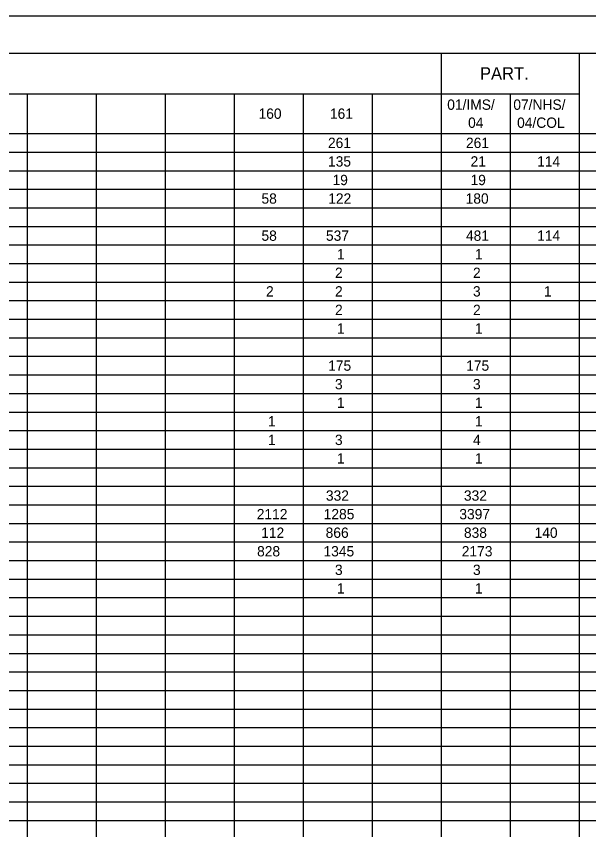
# Model space of a CAD drawing. Extents: x 1826847 to 2221677, y 500657 to 714743.
# Drawn here: x 1827314 to 1827702, y 714191 to 714743 of the extents above; entities that cross this region are included whole.
import ezdxf

# ---------------------------------------------------------------- set-up
doc = ezdxf.new("R2010")
doc.units = 0
for name, color, linetype in [('SH_Border', 7, 'Continuous'), ('SH_Cut_Line', 7, 'Continuous'), ('SH_Data', 7, 'Continuous'), ('SH_Text', 7, 'Continuous')]:
    doc.layers.add(name, color=color, linetype=linetype)

msp = doc.modelspace()

# ---------------------------------------------------------------- linework, layer by layer
at = {"layer": 'SH_Border'}
msp.add_lwpolyline([(1826946.62, 714718.08), (1828521.62, 714718.08), (1828521.62, 713668.08), (1826946.62, 713668.08)], close=True, dxfattribs=at)
at = {"layer": 'SH_Cut_Line'}
msp.add_lwpolyline([(1826846.62, 713643.08), (1828546.62, 713643.08), (1828546.62, 714743.08), (1826846.62, 714743.08)], close=True, dxfattribs=at)
at = {"layer": 'SH_Data'}
for p, q in [((1827274.22, 714718.08), (1827321.02, 714718.08)), ((1827321.02, 714718.08), (1827367.82, 714718.08)), ((1827367.82, 714718.08), (1827414.62, 714718.08)), ((1827414.62, 714718.08), (1827461.42, 714718.08)), ((1827461.42, 714718.08), (1827648.62, 714718.08)), ((1827601.82, 714718.08), (1827601.82, 714663.48)), ((1827648.62, 714718.08), (1827808.82, 714718.08)), ((1827695.42, 714718.08), (1827695.42, 714663.48)), ((1827274.22, 714690.48), (1827321.02, 714690.48)), ((1827321.02, 714690.48), (1827367.82, 714690.48)), ((1827321.02, 714690.48), (1827321.02, 714663.48)), ((1827367.82, 714690.48), (1827414.62, 714690.48)), ((1827367.82, 714690.48), (1827367.82, 714663.48)), ((1827414.62, 714690.48), (1827461.42, 714690.48)), ((1827414.62, 714690.48), (1827414.62, 714663.48)), ((1827461.42, 714690.48), (1827648.62, 714690.48)), ((1827461.42, 714690.48), (1827461.42, 714663.48)), ((1827508.22, 714690.48), (1827508.22, 714663.48)), ((1827555.02, 714690.48), (1827555.02, 714663.48)), ((1827648.62, 714690.48), (1827695.42, 714690.48)), ((1827648.62, 714690.48), (1827648.62, 714663.48)), ((1827274.22, 714663.48), (1827321.02, 714663.48)), ((1827321.02, 714663.48), (1827367.82, 714663.48)), ((1827321.02, 714663.48), (1827321.02, 714600.48)), ((1827367.82, 714663.48), (1827414.62, 714663.48)), ((1827367.82, 714663.48), (1827367.82, 714600.48)), ((1827414.62, 714663.48), (1827461.42, 714663.48)), ((1827414.62, 714663.48), (1827414.62, 714600.48)), ((1827461.42, 714663.48), (1827648.62, 714663.48)), ((1827461.42, 714663.48), (1827461.42, 714600.48)), ((1827508.22, 714663.48), (1827508.22, 714600.48)), ((1827555.02, 714663.48), (1827555.02, 714600.48)), ((1827601.82, 714663.48), (1827601.82, 714600.48)), ((1827648.62, 714663.48), (1827808.82, 714663.48)), ((1827648.62, 714663.48), (1827648.62, 714600.48)), ((1827695.42, 714663.48), (1827695.42, 714600.48)), ((1827274.22, 714650.88), (1827321.02, 714650.88)), ((1827321.02, 714650.88), (1827367.82, 714650.88)), ((1827367.82, 714650.88), (1827414.62, 714650.88)), ((1827414.62, 714650.88), (1827461.42, 714650.88)), ((1827461.42, 714650.88), (1827648.62, 714650.88)), ((1827648.62, 714650.88), (1827808.82, 714650.88)), ((1827274.22, 714638.28), (1827321.02, 714638.28)), ((1827321.02, 714638.28), (1827367.82, 714638.28)), ((1827367.82, 714638.28), (1827414.62, 714638.28)), ((1827414.62, 714638.28), (1827461.42, 714638.28)), ((1827461.42, 714638.28), (1827648.62, 714638.28)), ((1827648.62, 714638.28), (1827808.82, 714638.28)), ((1827274.22, 714625.68), (1827321.02, 714625.68)), ((1827321.02, 714625.68), (1827367.82, 714625.68)), ((1827367.82, 714625.68), (1827414.62, 714625.68)), ((1827414.62, 714625.68), (1827461.42, 714625.68)), ((1827461.42, 714625.68), (1827648.62, 714625.68)), ((1827648.62, 714625.68), (1827808.82, 714625.68)), ((1827274.22, 714613.08), (1827321.02, 714613.08)), ((1827321.02, 714613.08), (1827367.82, 714613.08)), ((1827367.82, 714613.08), (1827414.62, 714613.08)), ((1827414.62, 714613.08), (1827461.42, 714613.08)), ((1827461.42, 714613.08), (1827648.62, 714613.08)), ((1827648.62, 714613.08), (1827808.82, 714613.08)), ((1827274.22, 714600.48), (1827321.02, 714600.48)), ((1827321.02, 714600.48), (1827367.82, 714600.48)), ((1827321.02, 714600.48), (1827321.02, 714587.88)), ((1827367.82, 714600.48), (1827414.62, 714600.48)), ((1827367.82, 714600.48), (1827367.82, 714587.88)), ((1827414.62, 714600.48), (1827461.42, 714600.48)), ((1827414.62, 714600.48), (1827414.62, 714587.88)), ((1827461.42, 714600.48), (1827648.62, 714600.48)), ((1827461.42, 714600.48), (1827461.42, 714587.88)), ((1827508.22, 714600.48), (1827508.22, 714587.88)), ((1827555.02, 714600.48), (1827555.02, 714587.88)), ((1827601.82, 714600.48), (1827601.82, 714587.88)), ((1827648.62, 714600.48), (1827808.82, 714600.48)), ((1827648.62, 714600.48), (1827648.62, 714587.88)), ((1827695.42, 714600.48), (1827695.42, 714587.88)), ((1827274.22, 714587.88), (1827321.02, 714587.88)), ((1827321.02, 714587.88), (1827367.82, 714587.88)), ((1827321.02, 714587.88), (1827321.02, 714575.28)), ((1827367.82, 714587.88), (1827414.62, 714587.88)), ((1827367.82, 714587.88), (1827367.82, 714575.28)), ((1827414.62, 714587.88), (1827461.42, 714587.88)), ((1827414.62, 714587.88), (1827414.62, 714575.28)), ((1827461.42, 714587.88), (1827648.62, 714587.88)), ((1827461.42, 714587.88), (1827461.42, 714575.28)), ((1827508.22, 714587.88), (1827508.22, 714575.28)), ((1827555.02, 714587.88), (1827555.02, 714575.28)), ((1827601.82, 714587.88), (1827601.82, 714575.28)), ((1827648.62, 714587.88), (1827808.82, 714587.88)), ((1827648.62, 714587.88), (1827648.62, 714575.28)), ((1827695.42, 714587.88), (1827695.42, 714575.28)), ((1827274.22, 714575.28), (1827321.02, 714575.28)), ((1827321.02, 714575.28), (1827367.82, 714575.28)), ((1827321.02, 714575.28), (1827321.02, 714562.68)), ((1827367.82, 714575.28), (1827414.62, 714575.28)), ((1827367.82, 714575.28), (1827367.82, 714562.68)), ((1827414.62, 714575.28), (1827461.42, 714575.28)), ((1827414.62, 714575.28), (1827414.62, 714562.68)), ((1827461.42, 714575.28), (1827648.62, 714575.28)), ((1827461.42, 714575.28), (1827461.42, 714562.68)), ((1827508.22, 714575.28), (1827508.22, 714562.68)), ((1827555.02, 714575.28), (1827555.02, 714562.68)), ((1827601.82, 714575.28), (1827601.82, 714562.68)), ((1827648.62, 714575.28), (1827808.82, 714575.28)), ((1827648.62, 714575.28), (1827648.62, 714562.68)), ((1827695.42, 714575.28), (1827695.42, 714562.68)), ((1827274.22, 714562.68), (1827321.02, 714562.68)), ((1827321.02, 714562.68), (1827367.82, 714562.68)), ((1827321.02, 714562.68), (1827321.02, 714550.08)), ((1827367.82, 714562.68), (1827414.62, 714562.68)), ((1827367.82, 714562.68), (1827367.82, 714550.08)), ((1827414.62, 714562.68), (1827461.42, 714562.68)), ((1827414.62, 714562.68), (1827414.62, 714550.08)), ((1827461.42, 714562.68), (1827648.62, 714562.68)), ((1827461.42, 714562.68), (1827461.42, 714550.08)), ((1827508.22, 714562.68), (1827508.22, 714550.08)), ((1827555.02, 714562.68), (1827555.02, 714550.08)), ((1827601.82, 714562.68), (1827601.82, 714550.08)), ((1827648.62, 714562.68), (1827808.82, 714562.68)), ((1827648.62, 714562.68), (1827648.62, 714550.08)), ((1827695.42, 714562.68), (1827695.42, 714550.08)), ((1827274.22, 714550.08), (1827321.02, 714550.08)), ((1827321.02, 714550.08), (1827367.82, 714550.08)), ((1827321.02, 714550.08), (1827321.02, 714537.48)), ((1827367.82, 714550.08), (1827414.62, 714550.08)), ((1827367.82, 714550.08), (1827367.82, 714537.48)), ((1827414.62, 714550.08), (1827461.42, 714550.08)), ((1827414.62, 714550.08), (1827414.62, 714537.48)), ((1827461.42, 714550.08), (1827648.62, 714550.08)), ((1827461.42, 714550.08), (1827461.42, 714537.48)), ((1827508.22, 714550.08), (1827508.22, 714537.48)), ((1827555.02, 714550.08), (1827555.02, 714537.48)), ((1827601.82, 714550.08), (1827601.82, 714537.48)), ((1827648.62, 714550.08), (1827808.82, 714550.08)), ((1827648.62, 714550.08), (1827648.62, 714537.48)), ((1827695.42, 714550.08), (1827695.42, 714537.48)), ((1827274.22, 714537.48), (1827321.02, 714537.48)), ((1827321.02, 714537.48), (1827367.82, 714537.48)), ((1827321.02, 714537.48), (1827321.02, 714524.88)), ((1827367.82, 714537.48), (1827414.62, 714537.48)), ((1827367.82, 714537.48), (1827367.82, 714524.88)), ((1827414.62, 714537.48), (1827461.42, 714537.48)), ((1827414.62, 714537.48), (1827414.62, 714524.88)), ((1827461.42, 714537.48), (1827648.62, 714537.48)), ((1827461.42, 714537.48), (1827461.42, 714524.88)), ((1827508.22, 714537.48), (1827508.22, 714524.88)), ((1827555.02, 714537.48), (1827555.02, 714524.88)), ((1827601.82, 714537.48), (1827601.82, 714524.88)), ((1827648.62, 714537.48), (1827808.82, 714537.48)), ((1827648.62, 714537.48), (1827648.62, 714524.88)), ((1827695.42, 714537.48), (1827695.42, 714524.88)), ((1827274.22, 714524.88), (1827321.02, 714524.88)), ((1827321.02, 714524.88), (1827367.82, 714524.88)), ((1827321.02, 714524.88), (1827321.02, 714512.28)), ((1827367.82, 714524.88), (1827414.62, 714524.88)), ((1827367.82, 714524.88), (1827367.82, 714512.28)), ((1827414.62, 714524.88), (1827461.42, 714524.88)), ((1827414.62, 714524.88), (1827414.62, 714512.28)), ((1827461.42, 714524.88), (1827648.62, 714524.88)), ((1827461.42, 714524.88), (1827461.42, 714512.28)), ((1827508.22, 714524.88), (1827508.22, 714512.28)), ((1827555.02, 714524.88), (1827555.02, 714512.28)), ((1827601.82, 714524.88), (1827601.82, 714512.28)), ((1827648.62, 714524.88), (1827808.82, 714524.88)), ((1827648.62, 714524.88), (1827648.62, 714512.28)), ((1827695.42, 714524.88), (1827695.42, 714512.28)), ((1827274.22, 714512.28), (1827321.02, 714512.28)), ((1827321.02, 714512.28), (1827367.82, 714512.28)), ((1827321.02, 714512.28), (1827321.02, 714499.68)), ((1827367.82, 714512.28), (1827414.62, 714512.28)), ((1827367.82, 714512.28), (1827367.82, 714499.68)), ((1827414.62, 714512.28), (1827461.42, 714512.28)), ((1827414.62, 714512.28), (1827414.62, 714499.68)), ((1827461.42, 714512.28), (1827648.62, 714512.28)), ((1827461.42, 714512.28), (1827461.42, 714499.68)), ((1827508.22, 714512.28), (1827508.22, 714499.68)), ((1827555.02, 714512.28), (1827555.02, 714499.68)), ((1827601.82, 714512.28), (1827601.82, 714499.68)), ((1827648.62, 714512.28), (1827808.82, 714512.28)), ((1827648.62, 714512.28), (1827648.62, 714499.68)), ((1827695.42, 714512.28), (1827695.42, 714499.68)), ((1827274.22, 714499.68), (1827321.02, 714499.68)), ((1827321.02, 714499.68), (1827367.82, 714499.68)), ((1827321.02, 714499.68), (1827321.02, 714487.08)), ((1827367.82, 714499.68), (1827414.62, 714499.68)), ((1827367.82, 714499.68), (1827367.82, 714487.08)), ((1827414.62, 714499.68), (1827461.42, 714499.68)), ((1827414.62, 714499.68), (1827414.62, 714487.08)), ((1827461.42, 714499.68), (1827648.62, 714499.68)), ((1827461.42, 714499.68), (1827461.42, 714487.08)), ((1827508.22, 714499.68), (1827508.22, 714487.08)), ((1827555.02, 714499.68), (1827555.02, 714487.08)), ((1827601.82, 714499.68), (1827601.82, 714487.08)), ((1827648.62, 714499.68), (1827808.82, 714499.68)), ((1827648.62, 714499.68), (1827648.62, 714487.08)), ((1827695.42, 714499.68), (1827695.42, 714487.08)), ((1827274.22, 714487.08), (1827321.02, 714487.08)), ((1827321.02, 714487.08), (1827367.82, 714487.08)), ((1827321.02, 714487.08), (1827321.02, 714474.48)), ((1827367.82, 714487.08), (1827414.62, 714487.08)), ((1827367.82, 714487.08), (1827367.82, 714474.48)), ((1827414.62, 714487.08), (1827461.42, 714487.08)), ((1827414.62, 714487.08), (1827414.62, 714474.48)), ((1827461.42, 714487.08), (1827648.62, 714487.08)), ((1827461.42, 714487.08), (1827461.42, 714474.48)), ((1827508.22, 714487.08), (1827508.22, 714474.48)), ((1827555.02, 714487.08), (1827555.02, 714474.48)), ((1827601.82, 714487.08), (1827601.82, 714474.48)), ((1827648.62, 714487.08), (1827808.82, 714487.08)), ((1827648.62, 714487.08), (1827648.62, 714474.48)), ((1827695.42, 714487.08), (1827695.42, 714474.48)), ((1827274.22, 714474.48), (1827321.02, 714474.48)), ((1827321.02, 714474.48), (1827367.82, 714474.48)), ((1827321.02, 714474.48), (1827321.02, 714461.88)), ((1827367.82, 714474.48), (1827414.62, 714474.48)), ((1827367.82, 714474.48), (1827367.82, 714461.88)), ((1827414.62, 714474.48), (1827461.42, 714474.48)), ((1827414.62, 714474.48), (1827414.62, 714461.88)), ((1827461.42, 714474.48), (1827648.62, 714474.48)), ((1827461.42, 714474.48), (1827461.42, 714461.88)), ((1827508.22, 714474.48), (1827508.22, 714461.88)), ((1827555.02, 714474.48), (1827555.02, 714461.88)), ((1827601.82, 714474.48), (1827601.82, 714461.88)), ((1827648.62, 714474.48), (1827808.82, 714474.48)), ((1827648.62, 714474.48), (1827648.62, 714461.88)), ((1827695.42, 714474.48), (1827695.42, 714461.88)), ((1827274.22, 714461.88), (1827321.02, 714461.88)), ((1827321.02, 714461.88), (1827367.82, 714461.88)), ((1827321.02, 714461.88), (1827321.02, 714424.08)), ((1827367.82, 714461.88), (1827414.62, 714461.88)), ((1827367.82, 714461.88), (1827367.82, 714424.08)), ((1827414.62, 714461.88), (1827461.42, 714461.88)), ((1827414.62, 714461.88), (1827414.62, 714424.08)), ((1827461.42, 714461.88), (1827648.62, 714461.88)), ((1827461.42, 714461.88), (1827461.42, 714424.08)), ((1827508.22, 714461.88), (1827508.22, 714424.08)), ((1827555.02, 714461.88), (1827555.02, 714424.08)), ((1827601.82, 714461.88), (1827601.82, 714424.08)), ((1827648.62, 714461.88), (1827808.82, 714461.88)), ((1827648.62, 714461.88), (1827648.62, 714424.08)), ((1827695.42, 714461.88), (1827695.42, 714424.08)), ((1827274.22, 714449.28), (1827321.02, 714449.28)), ((1827321.02, 714449.28), (1827367.82, 714449.28)), ((1827367.82, 714449.28), (1827414.62, 714449.28)), ((1827414.62, 714449.28), (1827461.42, 714449.28)), ((1827461.42, 714449.28), (1827648.62, 714449.28)), ((1827648.62, 714449.28), (1827808.82, 714449.28)), ((1827274.22, 714436.68), (1827321.02, 714436.68)), ((1827321.02, 714436.68), (1827367.82, 714436.68)), ((1827367.82, 714436.68), (1827414.62, 714436.68)), ((1827414.62, 714436.68), (1827461.42, 714436.68)), ((1827461.42, 714436.68), (1827648.62, 714436.68)), ((1827648.62, 714436.68), (1827808.82, 714436.68)), ((1827274.22, 714424.08), (1827321.02, 714424.08)), ((1827321.02, 714424.08), (1827367.82, 714424.08)), ((1827321.02, 714424.08), (1827321.02, 714398.88)), ((1827367.82, 714424.08), (1827414.62, 714424.08)), ((1827367.82, 714424.08), (1827367.82, 714398.88)), ((1827414.62, 714424.08), (1827461.42, 714424.08)), ((1827414.62, 714424.08), (1827414.62, 714398.88)), ((1827461.42, 714424.08), (1827648.62, 714424.08)), ((1827461.42, 714424.08), (1827461.42, 714398.88)), ((1827508.22, 714424.08), (1827508.22, 714398.88)), ((1827555.02, 714424.08), (1827555.02, 714398.88)), ((1827601.82, 714424.08), (1827601.82, 714398.88)), ((1827648.62, 714424.08), (1827808.82, 714424.08)), ((1827648.62, 714424.08), (1827648.62, 714398.88)), ((1827695.42, 714424.08), (1827695.42, 714398.88)), ((1827274.22, 714411.48), (1827321.02, 714411.48)), ((1827321.02, 714411.48), (1827367.82, 714411.48)), ((1827367.82, 714411.48), (1827414.62, 714411.48)), ((1827414.62, 714411.48), (1827461.42, 714411.48)), ((1827461.42, 714411.48), (1827648.62, 714411.48)), ((1827648.62, 714411.48), (1827808.82, 714411.48)), ((1827274.22, 714398.88), (1827321.02, 714398.88)), ((1827321.02, 714398.88), (1827367.82, 714398.88)), ((1827321.02, 714398.88), (1827321.02, 714361.08)), ((1827367.82, 714398.88), (1827414.62, 714398.88)), ((1827367.82, 714398.88), (1827367.82, 714361.08)), ((1827414.62, 714398.88), (1827461.42, 714398.88)), ((1827414.62, 714398.88), (1827414.62, 714361.08)), ((1827461.42, 714398.88), (1827648.62, 714398.88)), ((1827461.42, 714398.88), (1827461.42, 714361.08)), ((1827508.22, 714398.88), (1827508.22, 714361.08)), ((1827555.02, 714398.88), (1827555.02, 714361.08)), ((1827601.82, 714398.88), (1827601.82, 714361.08)), ((1827648.62, 714398.88), (1827808.82, 714398.88)), ((1827648.62, 714398.88), (1827648.62, 714361.08)), ((1827695.42, 714398.88), (1827695.42, 714361.08)), ((1827274.22, 714386.28), (1827321.02, 714386.28)), ((1827321.02, 714386.28), (1827367.82, 714386.28)), ((1827367.82, 714386.28), (1827414.62, 714386.28)), ((1827414.62, 714386.28), (1827461.42, 714386.28)), ((1827461.42, 714386.28), (1827648.62, 714386.28)), ((1827648.62, 714386.28), (1827808.82, 714386.28)), ((1827274.22, 714373.68), (1827321.02, 714373.68)), ((1827321.02, 714373.68), (1827367.82, 714373.68)), ((1827367.82, 714373.68), (1827414.62, 714373.68)), ((1827414.62, 714373.68), (1827461.42, 714373.68)), ((1827461.42, 714373.68), (1827648.62, 714373.68)), ((1827648.62, 714373.68), (1827808.82, 714373.68)), ((1827274.22, 714361.08), (1827321.02, 714361.08)), ((1827321.02, 714361.08), (1827367.82, 714361.08)), ((1827321.02, 714361.08), (1827321.02, 714335.88)), ((1827367.82, 714361.08), (1827414.62, 714361.08)), ((1827367.82, 714361.08), (1827367.82, 714335.88)), ((1827414.62, 714361.08), (1827461.42, 714361.08)), ((1827414.62, 714361.08), (1827414.62, 714335.88)), ((1827461.42, 714361.08), (1827648.62, 714361.08)), ((1827461.42, 714361.08), (1827461.42, 714335.88)), ((1827508.22, 714361.08), (1827508.22, 714335.88)), ((1827555.02, 714361.08), (1827555.02, 714335.88)), ((1827601.82, 714361.08), (1827601.82, 714335.88)), ((1827648.62, 714361.08), (1827808.82, 714361.08)), ((1827648.62, 714361.08), (1827648.62, 714335.88)), ((1827695.42, 714361.08), (1827695.42, 714335.88)), ((1827274.22, 714348.48), (1827321.02, 714348.48)), ((1827321.02, 714348.48), (1827367.82, 714348.48)), ((1827367.82, 714348.48), (1827414.62, 714348.48)), ((1827414.62, 714348.48), (1827461.42, 714348.48)), ((1827461.42, 714348.48), (1827648.62, 714348.48)), ((1827648.62, 714348.48), (1827808.82, 714348.48)), ((1827274.22, 714335.88), (1827321.02, 714335.88)), ((1827321.02, 714335.88), (1827367.82, 714335.88)), ((1827321.02, 714335.88), (1827321.02, 714298.08)), ((1827367.82, 714335.88), (1827414.62, 714335.88)), ((1827367.82, 714335.88), (1827367.82, 714298.08)), ((1827414.62, 714335.88), (1827461.42, 714335.88)), ((1827414.62, 714335.88), (1827414.62, 714298.08)), ((1827461.42, 714335.88), (1827648.62, 714335.88)), ((1827461.42, 714335.88), (1827461.42, 714298.08)), ((1827508.22, 714335.88), (1827508.22, 714298.08)), ((1827555.02, 714335.88), (1827555.02, 714298.08)), ((1827601.82, 714335.88), (1827601.82, 714298.08)), ((1827648.62, 714335.88), (1827808.82, 714335.88)), ((1827648.62, 714335.88), (1827648.62, 714298.08)), ((1827695.42, 714335.88), (1827695.42, 714298.08)), ((1827274.22, 714323.28), (1827321.02, 714323.28)), ((1827321.02, 714323.28), (1827367.82, 714323.28)), ((1827367.82, 714323.28), (1827414.62, 714323.28)), ((1827414.62, 714323.28), (1827461.42, 714323.28)), ((1827461.42, 714323.28), (1827648.62, 714323.28)), ((1827648.62, 714323.28), (1827808.82, 714323.28)), ((1827274.22, 714310.68), (1827321.02, 714310.68)), ((1827321.02, 714310.68), (1827367.82, 714310.68)), ((1827367.82, 714310.68), (1827414.62, 714310.68)), ((1827414.62, 714310.68), (1827461.42, 714310.68)), ((1827461.42, 714310.68), (1827648.62, 714310.68)), ((1827648.62, 714310.68), (1827808.82, 714310.68)), ((1827274.22, 714298.08), (1827321.02, 714298.08)), ((1827321.02, 714298.08), (1827367.82, 714298.08)), ((1827321.02, 714298.08), (1827321.02, 714285.48)), ((1827367.82, 714298.08), (1827414.62, 714298.08)), ((1827367.82, 714298.08), (1827367.82, 714285.48)), ((1827414.62, 714298.08), (1827461.42, 714298.08)), ((1827414.62, 714298.08), (1827414.62, 714285.48)), ((1827461.42, 714298.08), (1827648.62, 714298.08)), ((1827461.42, 714298.08), (1827461.42, 714285.48)), ((1827508.22, 714298.08), (1827508.22, 714285.48)), ((1827555.02, 714298.08), (1827555.02, 714285.48)), ((1827601.82, 714298.08), (1827601.82, 714285.48)), ((1827648.62, 714298.08), (1827808.82, 714298.08)), ((1827648.62, 714298.08), (1827648.62, 714285.48)), ((1827695.42, 714298.08), (1827695.42, 714285.48)), ((1827274.22, 714285.48), (1827321.02, 714285.48)), ((1827321.02, 714285.48), (1827367.82, 714285.48)), ((1827321.02, 714285.48), (1827321.02, 714222.48)), ((1827367.82, 714285.48), (1827414.62, 714285.48)), ((1827367.82, 714285.48), (1827367.82, 714222.48)), ((1827414.62, 714285.48), (1827461.42, 714285.48)), ((1827414.62, 714285.48), (1827414.62, 714222.48)), ((1827461.42, 714285.48), (1827648.62, 714285.48)), ((1827461.42, 714285.48), (1827461.42, 714222.48)), ((1827508.22, 714285.48), (1827508.22, 714222.48)), ((1827555.02, 714285.48), (1827555.02, 714222.48)), ((1827601.82, 714285.48), (1827601.82, 714222.48)), ((1827648.62, 714285.48), (1827808.82, 714285.48)), ((1827648.62, 714285.48), (1827648.62, 714222.48)), ((1827695.42, 714285.48), (1827695.42, 714222.48)), ((1827274.22, 714272.88), (1827321.02, 714272.88)), ((1827321.02, 714272.88), (1827367.82, 714272.88)), ((1827367.82, 714272.88), (1827414.62, 714272.88)), ((1827414.62, 714272.88), (1827461.42, 714272.88)), ((1827461.42, 714272.88), (1827648.62, 714272.88)), ((1827648.62, 714272.88), (1827808.82, 714272.88)), ((1827274.22, 714260.28), (1827321.02, 714260.28)), ((1827321.02, 714260.28), (1827367.82, 714260.28)), ((1827367.82, 714260.28), (1827414.62, 714260.28)), ((1827414.62, 714260.28), (1827461.42, 714260.28)), ((1827461.42, 714260.28), (1827648.62, 714260.28)), ((1827648.62, 714260.28), (1827808.82, 714260.28)), ((1827274.22, 714247.68), (1827321.02, 714247.68)), ((1827321.02, 714247.68), (1827367.82, 714247.68)), ((1827367.82, 714247.68), (1827414.62, 714247.68)), ((1827414.62, 714247.68), (1827461.42, 714247.68)), ((1827461.42, 714247.68), (1827648.62, 714247.68)), ((1827648.62, 714247.68), (1827808.82, 714247.68)), ((1827274.22, 714235.08), (1827321.02, 714235.08)), ((1827321.02, 714235.08), (1827367.82, 714235.08)), ((1827367.82, 714235.08), (1827414.62, 714235.08)), ((1827414.62, 714235.08), (1827461.42, 714235.08)), ((1827461.42, 714235.08), (1827648.62, 714235.08)), ((1827648.62, 714235.08), (1827808.82, 714235.08)), ((1827274.22, 714222.48), (1827321.02, 714222.48)), ((1827321.02, 714222.48), (1827367.82, 714222.48)), ((1827321.02, 714222.48), (1827321.02, 714159.48)), ((1827367.82, 714222.48), (1827414.62, 714222.48)), ((1827367.82, 714222.48), (1827367.82, 714159.48)), ((1827414.62, 714222.48), (1827461.42, 714222.48)), ((1827414.62, 714222.48), (1827414.62, 714159.48)), ((1827461.42, 714222.48), (1827648.62, 714222.48)), ((1827461.42, 714222.48), (1827461.42, 714159.48)), ((1827508.22, 714222.48), (1827508.22, 714159.48)), ((1827555.02, 714222.48), (1827555.02, 714159.48)), ((1827601.82, 714222.48), (1827601.82, 714159.48)), ((1827648.62, 714222.48), (1827808.82, 714222.48)), ((1827648.62, 714222.48), (1827648.62, 714159.48)), ((1827695.42, 714222.48), (1827695.42, 714159.48)), ((1827274.22, 714209.88), (1827321.02, 714209.88)), ((1827321.02, 714209.88), (1827367.82, 714209.88)), ((1827367.82, 714209.88), (1827414.62, 714209.88)), ((1827414.62, 714209.88), (1827461.42, 714209.88)), ((1827461.42, 714209.88), (1827648.62, 714209.88)), ((1827648.62, 714209.88), (1827808.82, 714209.88)), ((1827274.22, 714197.28), (1827321.02, 714197.28)), ((1827321.02, 714197.28), (1827367.82, 714197.28)), ((1827367.82, 714197.28), (1827414.62, 714197.28)), ((1827414.62, 714197.28), (1827461.42, 714197.28)), ((1827461.42, 714197.28), (1827648.62, 714197.28)), ((1827648.62, 714197.28), (1827808.82, 714197.28))]:
    msp.add_line(p, q, dxfattribs=at)

# ---------------------------------------------------------------- texts
at = {"layer": 'SH_Text'}
for s, height, p in [('PART.', 8.4, (1827628.05, 714700.08)), ('01/IMS/', 7, (1827605.85, 714679.6)), ('07/NHS/', 7, (1827650.69, 714679.6)), ('160', 7, (1827477.87, 714673.48)), ('161', 7, (1827526.29, 714673.48)), ('04', 7, (1827619.98, 714667.35)), ('04/COL', 7, (1827653.22, 714667.35)), ('261', 7, (1827524.97, 714653.68)), ('261', 7, (1827618.57, 714653.68)), ('135', 7, (1827524.98, 714641.08)), ('21', 7, (1827621.65, 714641.08)), ('114', 7, (1827666.84, 714641.08)), ('19', 7, (1827528.04, 714628.48)), ('19', 7, (1827621.64, 714628.48)), ('58', 7, (1827479.86, 714615.88)), ('122', 7, (1827525.11, 714615.88)), ('180', 7, (1827618.33, 714615.88)), ('58', 7, (1827479.86, 714590.68)), ('537', 7, (1827523.6, 714590.68)), ('481', 7, (1827618.54, 714590.68)), ('114', 7, (1827666.84, 714590.68)), ('1', 7, (1827531.03, 714578.08)), ('1', 7, (1827624.63, 714578.08)), ('2', 7, (1827529.74, 714565.48)), ('2', 7, (1827623.34, 714565.48)), ('2', 7, (1827482.94, 714552.88)), ('2', 7, (1827529.74, 714552.88)), ('3', 7, (1827623.31, 714552.88)), ('1', 7, (1827671.43, 714552.88)), ('2', 7, (1827529.74, 714540.28)), ('2', 7, (1827623.34, 714540.28)), ('1', 7, (1827531.03, 714527.68)), ('1', 7, (1827624.63, 714527.68)), ('175', 7, (1827525.09, 714502.48)), ('175', 7, (1827618.69, 714502.48)), ('3', 7, (1827529.71, 714489.88)), ('3', 7, (1827623.31, 714489.88)), ('1', 7, (1827531.03, 714477.28)), ('1', 7, (1827624.63, 714477.28)), ('1', 7, (1827484.23, 714464.68)), ('1', 7, (1827624.63, 714464.68)), ('1', 7, (1827484.23, 714452.08)), ('3', 7, (1827529.71, 714452.08)), ('4', 7, (1827623.34, 714452.08)), ('1', 7, (1827531.03, 714439.48)), ('1', 7, (1827624.63, 714439.48)), ('332', 7, (1827523.57, 714414.28)), ('332', 7, (1827617.17, 714414.28)), ('2112', 7, (1827476.66, 714401.68)), ('1285', 7, (1827522.06, 714401.68)), ('3397', 7, (1827614.06, 714401.68)), ('112', 7, (1827479.64, 714389.08)), ('866', 7, (1827523.38, 714389.08)), ('838', 7, (1827617.17, 714389.08)), ('140', 7, (1827665.1, 714389.08)), ('828', 7, (1827476.88, 714376.48)), ('1345', 7, (1827521.92, 714376.48)), ('2173', 7, (1827615.71, 714376.48)), ('3', 7, (1827529.71, 714363.88)), ('3', 7, (1827623.31, 714363.88)), ('1', 7, (1827531.03, 714351.28)), ('1', 7, (1827624.63, 714351.28))]:
    msp.add_text(s, height=height, dxfattribs=at).set_placement(p)

doc.saveas('drawing.dxf')
